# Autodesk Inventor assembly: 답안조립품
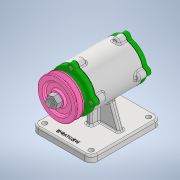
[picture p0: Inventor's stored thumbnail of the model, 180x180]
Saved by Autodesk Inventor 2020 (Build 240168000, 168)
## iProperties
Created: 2022-11
Part Number: 답안조립품
Document SubType Name: Assembly
Designer: Owner
Author: Owner
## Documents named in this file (12)
- C:\Users\Owner\Desktop\721108V1015\답안조립품.iam
- C:\Users\Owner\Desktop\721108V1015\본체.ipt
- C:\Users\Owner\Desktop\721108V1015\V-벨트풀리.ipt
- C:\Users\Owner\Desktop\721108V1015\개스킷.ipt
- C:\Users\Owner\Desktop\721108V1015\너트 M12 x 1.25.ipt
- C:\Users\Owner\Desktop\721108V1015\뒤커버.ipt
- C:\Users\Owner\Desktop\721108V1015\베어링 6204.ipt
- C:\Users\Owner\Desktop\721108V1015\볼트 M4 x 12.ipt
- C:\Users\Owner\Desktop\721108V1015\앞커버.ipt
- C:\Users\Owner\Desktop\721108V1015\오일 실.ipt
- C:\Users\Owner\Desktop\721108V1015\축.ipt
- C:\Users\Owner\Desktop\721108V1015\키 4 x 4.ipt
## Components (8 placed, 6 different names)
1. V-벨트풀리:1
2. 개스킷:1
3. KS B 1012 클래스 1 일반 - 미터 M12x1.25:1
4. KS B 2023 6204 - 20 x 47 x 14:1
5. KS B 2804 D D - 20 32 8:1
6. KS B 1311 (I) 4 x 4 x 12:1
7. 개스킷:2
8. KS B 2023 6204 - 20 x 47 x 14:2
